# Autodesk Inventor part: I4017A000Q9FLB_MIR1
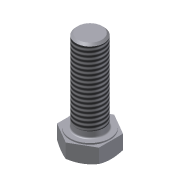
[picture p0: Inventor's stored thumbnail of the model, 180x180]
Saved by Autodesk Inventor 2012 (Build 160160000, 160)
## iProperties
Company: CAD-Verlag
Shininess: 64.0
Length Units: 11269
Angle Units: 11279
Time Units: 11290
Mass Units: 11283
Length Display Precision: 3
Angle Display Precision: 2
Compacted: True
Part Number: I4017A000Q9FLB_MIR1
Document SubType Name: Modeling
Created: 2004-09
Material: Steel, Mild
Designer: Greiling
Manufacturer: Standard
Standards Organization: Custom
Density: 1 g/cm^3
Density: 0.0
Volumn: 0.0
Area: 0.0
PropertySet Name: Model Information
Control State: 0
Master: False
Checked Out: False
Author: Jürgen Kronas
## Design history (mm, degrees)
node "Sechskantschraube DIN EN ISO 4017 - M12x35" dims "d0" = 10, "d28" = 0
  node "WorkPlane1"
  node "MSC_PF1"
  node "MSC_PT1"
  node "MSC_A1"
  node "WorkAxis1"
  node "WorkPoint1"
node "Volumenkörper1"
node "Volumenkörpern"
node "Oberflächenkörpern"
tag "Bezeichnung2"
feature "Volumenkörper1::Sechskantschraube DIN EN ISO 4017 - M12x35" dims "d0" = 10, "d28" = 0
